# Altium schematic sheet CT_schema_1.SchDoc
size 486 x 258 mm
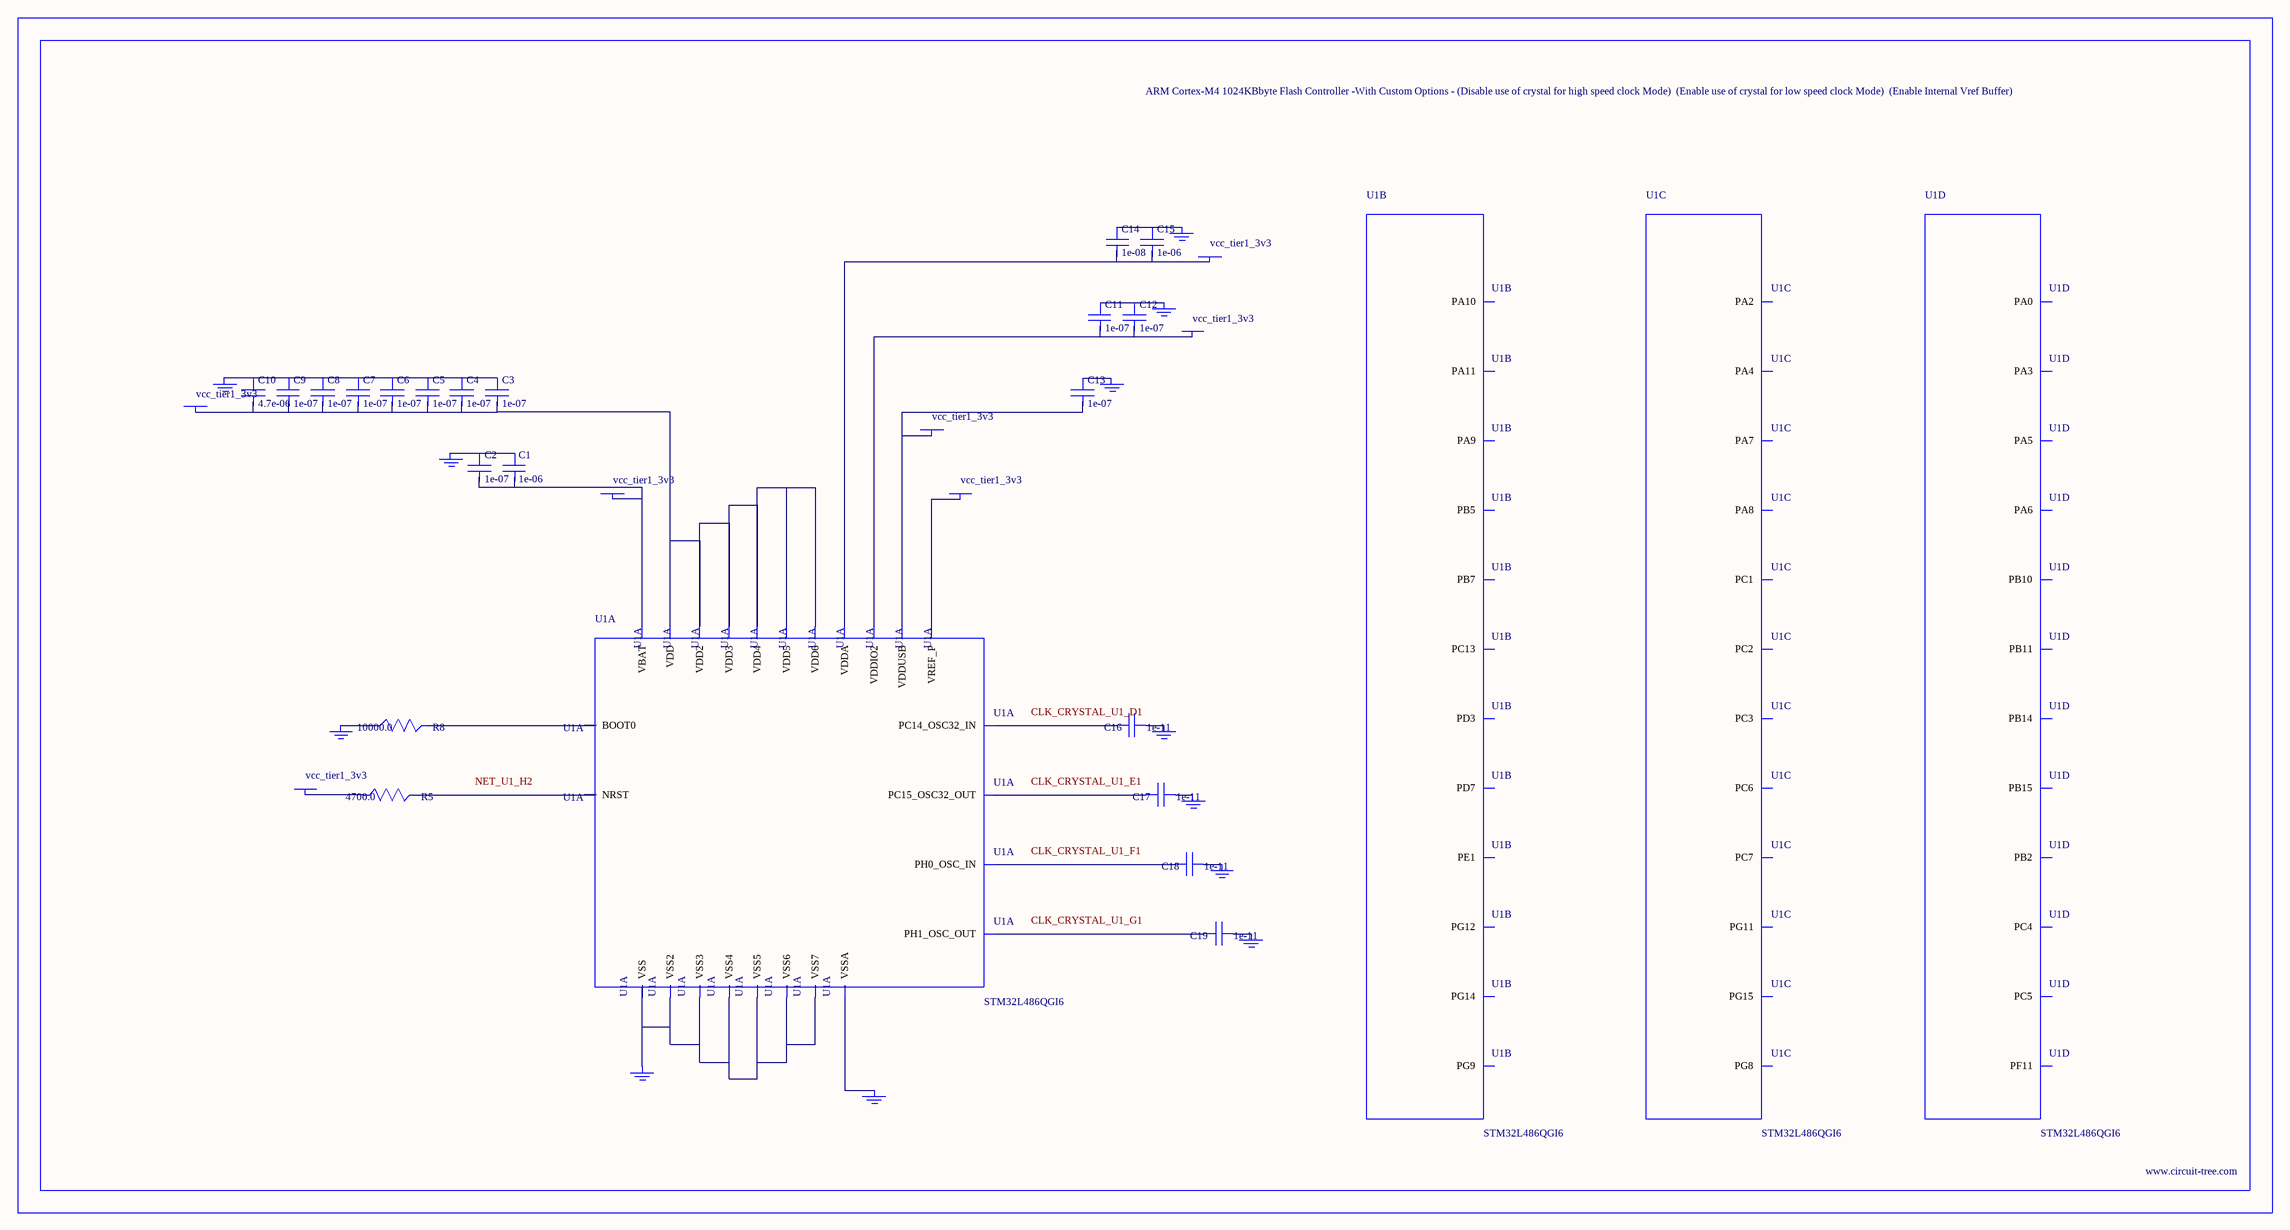
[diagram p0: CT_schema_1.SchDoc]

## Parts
BORDER0  (no value)
C1  1e-06  [C0603]
C2  1e-07  [C0603]
C3  1e-07  [C0603]
C4  1e-07  [C0603]
C5  1e-07  [C0603]
C6  1e-07  [C0603]
C7  1e-07  [C0603]
C8  1e-07  [C0603]
C9  1e-07  [C0603]
C10  4.7e-06  [C0603]
C11  1e-07  [C0603]
C12  1e-07  [C0603]
C13  1e-07  [C0603]
C14  1e-08  [C0603]
C15  1e-06  [C0603]
C16  1e-11  [C0402]
C17  1e-11  [C0402]
C18  1e-11  [C0402]
C19  1e-11  [C0402]
GND_INSTANCE_0_0  (no value)
GND_INSTANCE_0_1  (no value)
GND_INSTANCE_0_2  (no value)
GND_INSTANCE_0_3  (no value)
GND_INSTANCE_0_4  (no value)
GND_INSTANCE_0_5  (no value)
GND_INSTANCE_0_6  (no value)
GND_INSTANCE_0_7  (no value)
GND_INSTANCE_0_8  (no value)
GND_INSTANCE_0_9  (no value)
GND_INSTANCE_0_10  (no value)
GND_INSTANCE_0_11  (no value)
POWER_INSTANCE_0_0  vcc_tier1_3v3
POWER_INSTANCE_0_1  vcc_tier1_3v3
POWER_INSTANCE_0_2  vcc_tier1_3v3
POWER_INSTANCE_0_3  vcc_tier1_3v3
POWER_INSTANCE_0_4  vcc_tier1_3v3
POWER_INSTANCE_0_5  vcc_tier1_3v3
POWER_INSTANCE_0_6  vcc_tier1_3v3
R5  4700.0  [R0603]
R8  10000.0  [R0603]
U1  STM32L486QGI6  [UFBGA132]  (parts A,B,C,D of 13)

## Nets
NetC1_1: C1.1 C2.1 GND_INSTANCE_0_0.0(GND)
NetC1_2: C1.2 C2.2 POWER_INSTANCE_0_0.0(PWR) U1.E2(VBAT)
NetC3_1: C3.1 C4.1 C5.1 C6.1 C7.1 C8.1 C9.1 C10.1 GND_INSTANCE_0_1.0(GND)
NetC3_2: C3.2 C4.2 C5.2 C6.2 C7.2 C8.2 C9.2 C10.2 POWER_INSTANCE_0_1.0(PWR) U1.C4(VDD) U1.G2(VDD4) U1.G6(VDD5) U1.G11(VDD2) U1.G12(VDD3) U1.H3(VDD6)
NetC11_1: C11.1 C12.1 GND_INSTANCE_0_2.0(GND)
NetC11_2: C11.2 C12.2 POWER_INSTANCE_0_2.0(PWR) U1.G7(VDDIO2)
NetC13_1: C13.1 GND_INSTANCE_0_4.0(GND)
NetC13_2: C13.2 POWER_INSTANCE_0_3.0(PWR) U1.C11(VDDUSB)
NetC14_1: C14.1 C15.1 GND_INSTANCE_0_5.0(GND)
NetC14_2: C14.2 C15.2 POWER_INSTANCE_0_4.0(PWR) U1.M1(VDDA)
NetC16_1: C16.1 GND_INSTANCE_0_6.0(GND)
NetC16_2: C16.2 U1.D1(PC14_OSC32_IN)
NetC17_1: C17.1 GND_INSTANCE_0_7.0(GND)
NetC17_2: C17.2 U1.E1(PC15_OSC32_OUT)
NetC18_1: C18.1 GND_INSTANCE_0_8.0(GND)
NetC18_2: C18.2 U1.F1(PH0_OSC_IN)
NetC19_1: C19.1 GND_INSTANCE_0_9.0(GND)
NetC19_2: C19.2 U1.G1(PH1_OSC_OUT)
NetGND_INSTANCE_0_3_0: GND_INSTANCE_0_3.0(GND) R8.1
NetGND_INSTANCE_0_10_0: GND_INSTANCE_0_10.0(GND) U1.J1(VSSA)
NetGND_INSTANCE_0_11_0: GND_INSTANCE_0_11.0(GND) U1.D3(VSS) U1.E3(VSS2) U1.F2(VSS5) U1.F6(VSS6) U1.F7(VSS7) U1.F11(VSS3) U1.F12(VSS4)
NetPOWER_INSTANCE_0_5_0: POWER_INSTANCE_0_5.0(PWR) U1.L1(VREF_P)
NetPOWER_INSTANCE_0_6_0: POWER_INSTANCE_0_6.0(PWR) R5.1
NetR5_2: R5.2 U1.H2(NRST)
NetR8_2: R8.2 U1.A4(BOOT0)

Not connected (* = marked no-connect by the designer): U1 A2(PE1) A5(PD7) B4(PB7) B8(PD3) B12(PA11) C1(PC13) C5(PB5) C6(PG14) C12(PA10) D7(PG12) D9(PG9) D10(PA9) D11(PA8) E11(PC7) E12(PC6) G3(PG11) J2(PC1) J3(PC2) J4(PA4) J5(PA7) J6(PG8) K1(PG15) K2(PC3) K3(PA2) K4(PA5) K5(PC4) K6(PF11) K10(PB15) K11(PB14) L2(PA0) L3(PA3) L4(PA6) L5(PC5) L6(PB2) L10(PB10) L11(PB11)

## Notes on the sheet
- Labels drawn without touching a wire or pin: CLK_CRYSTAL_U1_D1, CLK_CRYSTAL_U1_E1, CLK_CRYSTAL_U1_F1, CLK_CRYSTAL_U1_G1, NET_U1_H2

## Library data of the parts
BORDER0 = BORDER_PAGE0
C1 C15 = C0603C105K3RACTU
C2-C9 C11-C13 = 06035C104K4Z2A
C10 = GRM188R6YA475KE15D
C14 = 06035C103K4Z2A
C16-C19 = C0402C100K3GACTU
GND_INSTANCE_0_0-GND_INSTANCE_0_11 = GND
POWER_INSTANCE_0_0-POWER_INSTANCE_0_6 = PWR
R5 = RC0603JR-074K7L
R8 = RC0603JR-0710KL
